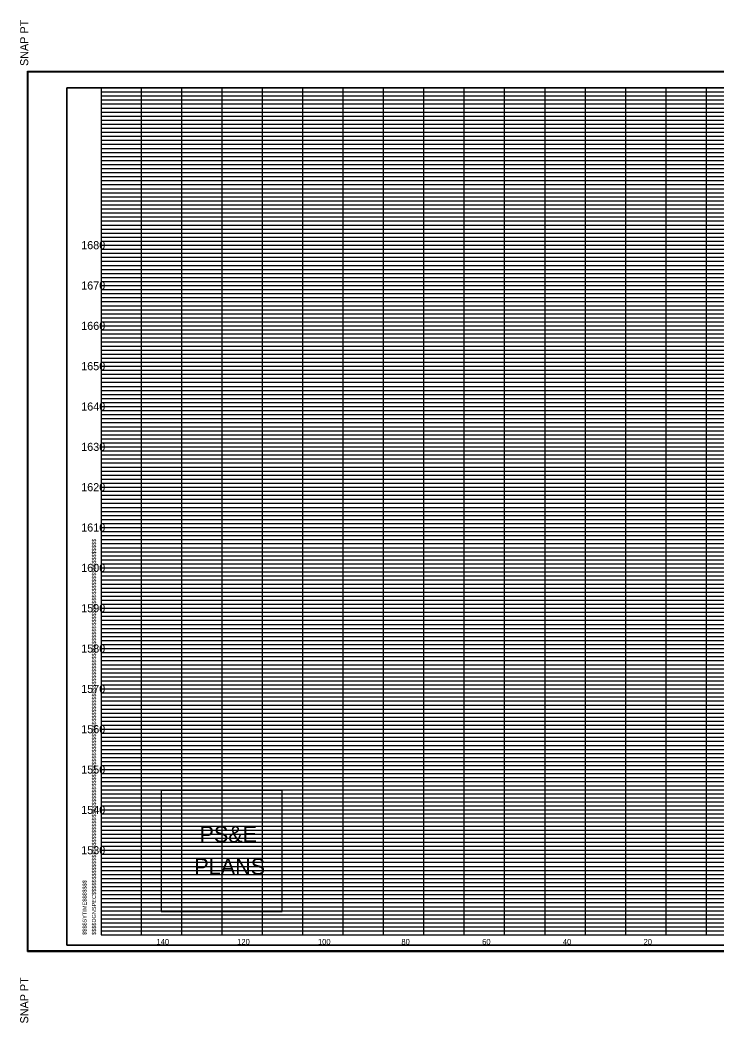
# Model space of a CAD drawing. Extents: x 980 to 1380, y 1248 to 3387.
# Drawn here: x 979.9 to 1152.6, y 1788.2 to 2036.8 of the extents above; entities that cross this region are included whole.
import ezdxf

# ---------------------------------------------------------------- set-up
doc = ezdxf.new("R2010")
doc.units = 0
for name, color, linetype in [('DESIGN - SHEET - Corner Text', 7, 'Continuous'), ('DESIGN - SHEET - Light Grid', 7, 'Continuous'), ('DESIGN - SHEET - Linework', 7, 'Continuous'), ('DESIGN - SHEET - Plot Shape', 7, 'Continuous'), ('DESIGN - TYPICAL - Text', 7, 'Continuous')]:
    doc.layers.add(name, color=color, linetype=linetype)

# ---------------------------------------------------------------- blocks, each defined once
blk = doc.blocks.new('XSTSHT')
at = {"layer": 'DESIGN - SHEET - Light Grid'}
for p, q in [((0, 20.9), (8, 20.9)), ((8, 20.9), (16, 20.9)), ((0, 20.8), (8, 20.8)), ((0, 20.7), (8, 20.7)), ((8, 20.8), (16, 20.8)), ((8, 20.7), (16, 20.7)), ((0, 20.6), (8, 20.6)), ((0, 20.5), (8, 20.5)), ((0, 20.4), (8, 20.4)), ((8, 20.6), (16, 20.6)), ((8, 20.5), (16, 20.5)), ((8, 20.4), (16, 20.4)), ((0, 20.3), (8, 20.3)), ((0, 20.2), (8, 20.2)), ((8, 20.3), (16, 20.3)), ((8, 20.2), (16, 20.2)), ((0, 20.1), (8, 20.1)), ((0, 19.9), (8, 19.9)), ((8, 20.1), (16, 20.1)), ((8, 19.9), (16, 19.9)), ((0, 19.8), (8, 19.8)), ((0, 19.7), (8, 19.7)), ((8, 19.8), (16, 19.8)), ((8, 19.7), (16, 19.7)), ((0, 19.6), (8, 19.6)), ((0, 19.5), (8, 19.5)), ((0, 19.4), (8, 19.4)), ((8, 19.6), (16, 19.6)), ((8, 19.5), (16, 19.5)), ((8, 19.4), (16, 19.4)), ((0, 19.3), (8, 19.3)), ((0, 19.2), (8, 19.2)), ((8, 19.3), (16, 19.3)), ((8, 19.2), (16, 19.2)), ((0, 19.1), (8, 19.1)), ((0, 18.9), (8, 18.9)), ((8, 19.1), (16, 19.1)), ((8, 18.9), (16, 18.9)), ((0, 18.8), (8, 18.8)), ((0, 18.7), (8, 18.7)), ((8, 18.8), (16, 18.8)), ((8, 18.7), (16, 18.7)), ((0, 18.6), (8, 18.6)), ((0, 18.5), (8, 18.5)), ((0, 18.4), (8, 18.4)), ((8, 18.6), (16, 18.6)), ((8, 18.5), (16, 18.5)), ((8, 18.4), (16, 18.4)), ((0, 18.3), (8, 18.3)), ((0, 18.2), (8, 18.2)), ((8, 18.3), (16, 18.3)), ((8, 18.2), (16, 18.2)), ((0, 18.1), (8, 18.1)), ((8, 18.1), (16, 18.1)), ((0, 17.9), (8, 17.9)), ((0, 17.8), (8, 17.8)), ((0, 17.7), (8, 17.7)), ((8, 17.9), (16, 17.9)), ((8, 17.8), (16, 17.8)), ((8, 17.7), (16, 17.7)), ((0, 17.6), (8, 17.6)), ((0, 17.5), (8, 17.5)), ((8, 17.6), (16, 17.6)), ((8, 17.5), (16, 17.5)), ((0, 17.4), (8, 17.4)), ((0, 17.3), (8, 17.3)), ((0, 17.2), (8, 17.2)), ((8, 17.4), (16, 17.4)), ((8, 17.3), (16, 17.3)), ((8, 17.2), (16, 17.2)), ((0, 17.1), (8, 17.1)), ((8, 17.1), (16, 17.1)), ((0, 16.9), (8, 16.9)), ((0, 16.8), (8, 16.8)), ((0, 16.7), (8, 16.7)), ((8, 16.9), (16, 16.9)), ((8, 16.8), (16, 16.8)), ((8, 16.7), (16, 16.7)), ((0, 16.6), (8, 16.6)), ((0, 16.5), (8, 16.5)), ((8, 16.6), (16, 16.6)), ((8, 16.5), (16, 16.5)), ((0, 16.4), (8, 16.4)), ((0, 16.3), (8, 16.3)), ((0, 16.2), (8, 16.2)), ((8, 16.4), (16, 16.4)), ((8, 16.3), (16, 16.3)), ((8, 16.2), (16, 16.2)), ((0, 16.1), (8, 16.1)), ((8, 16.1), (16, 16.1)), ((0, 15.9), (8, 15.9)), ((0, 15.8), (8, 15.8)), ((0, 15.7), (8, 15.7)), ((8, 15.9), (16, 15.9)), ((8, 15.8), (16, 15.8)), ((8, 15.7), (16, 15.7)), ((0, 15.6), (8, 15.6)), ((0, 15.5), (8, 15.5)), ((8, 15.6), (16, 15.6)), ((8, 15.5), (16, 15.5)), ((0, 15.4), (8, 15.4)), ((0, 15.3), (8, 15.3)), ((0, 15.2), (8, 15.2)), ((8, 15.4), (16, 15.4)), ((8, 15.3), (16, 15.3)), ((8, 15.2), (16, 15.2)), ((0, 15.1), (8, 15.1)), ((8, 15.1), (16, 15.1)), ((0, 14.9), (8, 14.9)), ((0, 14.8), (8, 14.8)), ((0, 14.7), (8, 14.7)), ((8, 14.9), (16, 14.9)), ((8, 14.8), (16, 14.8)), ((8, 14.7), (16, 14.7)), ((0, 14.6), (8, 14.6)), ((0, 14.5), (8, 14.5)), ((8, 14.6), (16, 14.6)), ((8, 14.5), (16, 14.5)), ((0, 14.4), (8, 14.4)), ((0, 14.3), (8, 14.3)), ((0, 14.2), (8, 14.2)), ((8, 14.4), (16, 14.4)), ((8, 14.3), (16, 14.3)), ((8, 14.2), (16, 14.2)), ((0, 14.1), (8, 14.1)), ((8, 14.1), (16, 14.1)), ((0, 13.9), (8, 13.9)), ((0, 13.8), (8, 13.8)), ((0, 13.7), (8, 13.7)), ((8, 13.9), (16, 13.9)), ((8, 13.8), (16, 13.8)), ((8, 13.7), (16, 13.7)), ((0, 13.6), (8, 13.6)), ((0, 13.5), (8, 13.5)), ((8, 13.6), (16, 13.6)), ((8, 13.5), (16, 13.5)), ((0, 13.4), (8, 13.4)), ((0, 13.3), (8, 13.3)), ((0, 13.2), (8, 13.2)), ((8, 13.4), (16, 13.4)), ((8, 13.3), (16, 13.3)), ((8, 13.2), (16, 13.2)), ((0, 13.1), (8, 13.1)), ((8, 13.1), (16, 13.1)), ((0, 12.9), (8, 12.9)), ((0, 12.8), (8, 12.8)), ((0, 12.7), (8, 12.7)), ((8, 12.9), (16, 12.9)), ((8, 12.8), (16, 12.8)), ((8, 12.7), (16, 12.7)), ((0, 12.6), (8, 12.6)), ((0, 12.5), (8, 12.5)), ((8, 12.6), (16, 12.6)), ((8, 12.5), (16, 12.5)), ((0, 12.4), (8, 12.4)), ((0, 12.3), (8, 12.3)), ((0, 12.2), (8, 12.2)), ((8, 12.4), (16, 12.4)), ((8, 12.3), (16, 12.3)), ((8, 12.2), (16, 12.2)), ((0, 12.1), (8, 12.1)), ((8, 12.1), (16, 12.1)), ((0, 11.9), (8, 11.9)), ((0, 11.8), (8, 11.8)), ((0, 11.7), (8, 11.7)), ((8, 11.9), (16, 11.9)), ((8, 11.8), (16, 11.8)), ((8, 11.7), (16, 11.7)), ((0, 11.6), (8, 11.6)), ((0, 11.5), (8, 11.5)), ((8, 11.6), (16, 11.6)), ((8, 11.5), (16, 11.5)), ((0, 11.4), (8, 11.4)), ((0, 11.3), (8, 11.3)), ((0, 11.2), (8, 11.2)), ((8, 11.4), (16, 11.4)), ((8, 11.3), (16, 11.3)), ((8, 11.2), (16, 11.2)), ((0, 11.1), (8, 11.1)), ((8, 11.1), (16, 11.1)), ((0, 10.9), (8, 10.9)), ((0, 10.8), (8, 10.8)), ((0, 10.7), (8, 10.7)), ((8, 10.9), (16, 10.9)), ((8, 10.8), (16, 10.8)), ((8, 10.7), (16, 10.7)), ((0, 10.6), (8, 10.6)), ((0, 10.5), (8, 10.5)), ((8, 10.6), (16, 10.6)), ((8, 10.5), (16, 10.5)), ((0, 10.4), (8, 10.4)), ((0, 10.3), (8, 10.3)), ((0, 10.2), (8, 10.2)), ((8, 10.4), (16, 10.4)), ((8, 10.3), (16, 10.3)), ((8, 10.2), (16, 10.2)), ((0, 10.1), (8, 10.1)), ((8, 10.1), (16, 10.1)), ((0, 9.9), (8, 9.9)), ((0, 9.8), (8, 9.8)), ((0, 9.7), (8, 9.7)), ((8, 9.9), (16, 9.9)), ((8, 9.8), (16, 9.8)), ((8, 9.7), (16, 9.7)), ((0, 9.6), (8, 9.6)), ((0, 9.5), (8, 9.5)), ((8, 9.6), (16, 9.6)), ((8, 9.5), (16, 9.5)), ((0, 9.4), (8, 9.4)), ((0, 9.3), (8, 9.3)), ((0, 9.2), (8, 9.2)), ((8, 9.4), (16, 9.4)), ((8, 9.3), (16, 9.3)), ((8, 9.2), (16, 9.2)), ((0, 9.1), (8, 9.1)), ((8, 9.1), (16, 9.1)), ((0, 8.9), (8, 8.9)), ((0, 8.8), (8, 8.8)), ((8, 8.9), (16, 8.9)), ((8, 8.8), (16, 8.8)), ((0, 8.7), (8, 8.7)), ((0, 8.6), (8, 8.6)), ((0, 8.5), (8, 8.5)), ((8, 8.7), (16, 8.7)), ((8, 8.6), (16, 8.6)), ((8, 8.5), (16, 8.5)), ((0, 8.4), (8, 8.4)), ((0, 8.3), (8, 8.3)), ((8, 8.4), (16, 8.4)), ((8, 8.3), (16, 8.3)), ((0, 8.2), (8, 8.2)), ((0, 8.1), (8, 8.1)), ((8, 8.2), (16, 8.2)), ((8, 8.1), (16, 8.1)), ((0, 7.9), (8, 7.9)), ((0, 7.8), (8, 7.8)), ((8, 7.9), (16, 7.9)), ((8, 7.8), (16, 7.8)), ((0, 7.7), (8, 7.7)), ((0, 7.6), (8, 7.6)), ((0, 7.5), (8, 7.5)), ((8, 7.7), (16, 7.7)), ((8, 7.6), (16, 7.6)), ((8, 7.5), (16, 7.5)), ((0, 7.4), (8, 7.4)), ((0, 7.3), (8, 7.3)), ((8, 7.4), (16, 7.4)), ((8, 7.3), (16, 7.3)), ((0, 7.2), (8, 7.2)), ((0, 7.1), (8, 7.1)), ((8, 7.2), (16, 7.2)), ((8, 7.1), (16, 7.1)), ((0, 6.9), (8, 6.9)), ((0, 6.8), (8, 6.8)), ((8, 6.9), (16, 6.9)), ((8, 6.8), (16, 6.8)), ((0, 6.7), (8, 6.7)), ((0, 6.6), (8, 6.6)), ((0, 6.5), (8, 6.5)), ((8, 6.7), (16, 6.7)), ((8, 6.6), (16, 6.6)), ((8, 6.5), (16, 6.5)), ((0, 6.4), (8, 6.4)), ((0, 6.3), (8, 6.3)), ((8, 6.4), (16, 6.4)), ((8, 6.3), (16, 6.3)), ((0, 6.2), (8, 6.2)), ((0, 6.1), (8, 6.1)), ((8, 6.2), (16, 6.2)), ((8, 6.1), (16, 6.1)), ((0, 5.9), (8, 5.9)), ((0, 5.8), (8, 5.8)), ((8, 5.9), (16, 5.9)), ((8, 5.8), (16, 5.8)), ((0, 5.7), (8, 5.7)), ((0, 5.6), (8, 5.6)), ((0, 5.5), (8, 5.5)), ((8, 5.7), (16, 5.7)), ((8, 5.6), (16, 5.6)), ((8, 5.5), (16, 5.5)), ((0, 5.4), (8, 5.4)), ((0, 5.3), (8, 5.3)), ((8, 5.4), (16, 5.4)), ((8, 5.3), (16, 5.3)), ((0, 5.2), (8, 5.2)), ((0, 5.1), (8, 5.1)), ((8, 5.2), (16, 5.2)), ((8, 5.1), (16, 5.1)), ((0, 4.9), (8, 4.9)), ((0, 4.8), (8, 4.8)), ((8, 4.9), (16, 4.9)), ((8, 4.8), (16, 4.8)), ((0, 4.7), (8, 4.7)), ((0, 4.6), (8, 4.6)), ((0, 4.5), (8, 4.5)), ((8, 4.7), (16, 4.7)), ((8, 4.6), (16, 4.6)), ((8, 4.5), (16, 4.5)), ((0, 4.4), (8, 4.4)), ((0, 4.3), (8, 4.3)), ((8, 4.4), (16, 4.4)), ((8, 4.3), (16, 4.3)), ((0, 4.2), (8, 4.2)), ((0, 4.1), (8, 4.1)), ((8, 4.2), (16, 4.2)), ((8, 4.1), (16, 4.1)), ((0, 3.9), (8, 3.9)), ((0, 3.8), (8, 3.8)), ((8, 3.9), (16, 3.9)), ((8, 3.8), (16, 3.8)), ((0, 3.7), (8, 3.7)), ((0, 3.6), (8, 3.6)), ((0, 3.5), (8, 3.5)), ((8, 3.7), (16, 3.7)), ((8, 3.6), (16, 3.6)), ((8, 3.5), (16, 3.5)), ((0, 3.4), (8, 3.4)), ((0, 3.3), (8, 3.3)), ((8, 3.4), (16, 3.4)), ((8, 3.3), (16, 3.3)), ((0, 3.2), (8, 3.2)), ((0, 3.1), (8, 3.1)), ((8, 3.2), (16, 3.2)), ((8, 3.1), (16, 3.1)), ((0, 2.9), (8, 2.9)), ((0, 2.8), (8, 2.8)), ((8, 2.9), (16, 2.9)), ((8, 2.8), (16, 2.8)), ((0, 2.7), (8, 2.7)), ((0, 2.6), (8, 2.6)), ((0, 2.5), (8, 2.5)), ((8, 2.7), (16, 2.7)), ((8, 2.6), (16, 2.6)), ((8, 2.5), (16, 2.5)), ((0, 2.4), (8, 2.4)), ((0, 2.3), (8, 2.3)), ((8, 2.4), (16, 2.4)), ((8, 2.3), (16, 2.3)), ((0, 2.2), (8, 2.2)), ((0, 2.1), (8, 2.1)), ((8, 2.2), (16, 2.2)), ((8, 2.1), (16, 2.1)), ((0, 1.9), (8, 1.9)), ((0, 1.8), (8, 1.8)), ((8, 1.9), (16, 1.9)), ((8, 1.8), (16, 1.8)), ((0, 1.7), (8, 1.7)), ((0, 1.6), (8, 1.6)), ((0, 1.5), (8, 1.5)), ((8, 1.7), (16, 1.7)), ((8, 1.6), (16, 1.6)), ((8, 1.5), (16, 1.5)), ((0, 1.4), (8, 1.4)), ((0, 1.3), (8, 1.3)), ((8, 1.4), (16, 1.4)), ((8, 1.3), (16, 1.3)), ((0, 1.2), (8, 1.2)), ((0, 1.1), (8, 1.1)), ((8, 1.2), (16, 1.2)), ((8, 1.1), (16, 1.1)), ((0, 0.9), (8, 0.9)), ((0, 0.8), (8, 0.8)), ((8, 0.9), (16, 0.9)), ((8, 0.8), (16, 0.8)), ((0, 0.7), (8, 0.7)), ((0, 0.6), (8, 0.6)), ((0, 0.5), (8, 0.5)), ((8, 0.7), (16, 0.7)), ((8, 0.6), (16, 0.6)), ((8, 0.5), (16, 0.5)), ((0, 0.4), (8, 0.4)), ((0, 0.3), (8, 0.3)), ((8, 0.4), (16, 0.4)), ((8, 0.3), (16, 0.3)), ((0, 0.2), (8, 0.2)), ((0, 0.1), (8, 0.1)), ((8, 0.2), (16, 0.2)), ((8, 0.1), (16, 0.1))]:
    blk.add_line(p, q, dxfattribs=at)
at = {"layer": 'DESIGN - SHEET - Linework'}
for p, q in [((-1.823, -0.414), (-1.823, 21.414)), ((-1.823, 21.414), (32.217, 21.414)), ((1, 0), (1, 21)), ((2, 0), (2, 21)), ((3, 0), (3, 21)), ((4, 0), (4, 21)), ((5, 0), (5, 21)), ((6, 0), (6, 21)), ((7, 0), (7, 21)), ((8, 0), (8, 21)), ((9, 0), (9, 21)), ((10, 0), (10, 21)), ((11, 0), (11, 21)), ((12, 0), (12, 21)), ((13, 0), (13, 21)), ((14, 0), (14, 21)), ((15, 0), (15, 21)), ((0, 20), (28, 20)), ((0, 19), (32, 19)), ((0, 18), (32, 18)), ((0, 17), (32, 17)), ((0, 16), (32, 16)), ((0, 15), (32, 15)), ((0, 14), (32, 14)), ((0, 13), (32, 13)), ((0, 12), (32, 12)), ((0, 11), (32, 11)), ((0, 10), (32, 10)), ((0, 9), (32, 9)), ((0, 8), (32, 8)), ((0, 7), (32, 7)), ((0, 6), (32, 6)), ((0, 5), (32, 5)), ((0, 4), (32, 4)), ((0, 3), (32, 3)), ((0, 2), (32, 2)), ((0, 1), (32, 1)), ((-1.823, -0.414), (32.217, -0.414))]:
    blk.add_line(p, q, dxfattribs=at)
blk.add_lwpolyline([(0, 21), (0, 0), (32, 0), (32, 21), (0, 21)], dxfattribs=at)
at = {"layer": 'DESIGN - SHEET - Plot Shape'}
for points in [[(-1.803, 21.394), (32.197, 21.394), (32.197, -0.394), (-1.803, -0.394)], [(-0.85, 21), (32, 21), (32, -0.25), (-0.85, -0.25)]]:
    blk.add_lwpolyline(points, close=True, dxfattribs=at)
at = {"layer": 'DESIGN - SHEET - Corner Text'}
for s, height, p in [('  SNAP PT', 0.2, (-1.803, 21.394)), ('$$$$DGNSPEC$$$$$$$$$$$$$$$$$$$$$$$$$$$$$$$$$$$$$$$$$$$$$$$$$$$$$$$$$$$$$$$$$$$$$$$$$$$$$$$$$$$$$$$$$$$$$$$$$$$$$$$$$$$$$$$$$$$', 0.100002, (-0.126, 0)), ('$$$$SYTIME$$$$$$$', 0.1, (-0.358, 0)), ('SNAP PT  ', 0.2, (-1.803, -2.194))]:
    blk.add_text(s, height=height, rotation=90, dxfattribs=at).set_placement(p)

msp = doc.modelspace()

# ---------------------------------------------------------------- linework, layer by layer
at = {"layer": 'DESIGN - SHEET - Corner Text'}
msp.add_lwpolyline([(1014.87, 1845.8), (1014.87, 1815.8), (1044.87, 1815.8), (1044.87, 1845.8)], close=True, dxfattribs=at)
at = {"layer": 'DESIGN - SHEET - Plot Shape'}
msp.add_lwpolyline([(991.5, 1807.5), (1320, 1807.5), (1320, 2020), (991.5, 2020)], close=True, dxfattribs=at)

# ---------------------------------------------------------------- block references
at = {"layer": 'DESIGN - TYPICAL - Text', "xscale": 10, "yscale": 10}
msp.add_blockref('XSTSHT', (1000, 1810), dxfattribs=at)

# ---------------------------------------------------------------- texts
at = {"layer": 'DESIGN - SHEET - Corner Text'}
for s, p in [('PS&E', (1024.39, 1832.97)), ('PLANS', (1023.11, 1824.97))]:
    msp.add_text(s, height=4, dxfattribs=at).set_placement(p)
at = {"layer": 'DESIGN - TYPICAL - Text'}
for s, height, p in [('     1680     ', 2, (991.37, 1980)), ('     1670     ', 2, (991.37, 1970)), ('     1660     ', 2, (991.37, 1960)), ('     1650     ', 2, (991.37, 1950)), ('     1640     ', 2, (991.37, 1940)), ('     1630     ', 2, (991.37, 1930)), ('     1620     ', 2, (991.37, 1920)), ('     1610     ', 2, (991.37, 1910)), ('     1600     ', 2, (991.37, 1900)), ('     1590     ', 2, (991.37, 1890)), ('     1580     ', 2, (991.37, 1880)), ('     1570     ', 2, (991.37, 1870)), ('     1560     ', 2, (991.37, 1860)), ('     1550     ', 2, (991.37, 1850)), ('     1540     ', 2, (991.37, 1840)), ('     1530     ', 2, (991.37, 1830)), ('     140     ', 1.4, (1011.14, 1807.6)), ('     120     ', 1.4, (1031.14, 1807.6)), ('     100     ', 1.4, (1051.14, 1807.6)), ('     80     ', 1.4, (1071.82, 1807.6)), ('     60     ', 1.4, (1091.82, 1807.6)), ('     40     ', 1.4, (1111.82, 1807.6)), ('     20     ', 1.4, (1131.82, 1807.6))]:
    msp.add_text(s, height=height, dxfattribs=at).set_placement(p)

doc.saveas('drawing.dxf')
